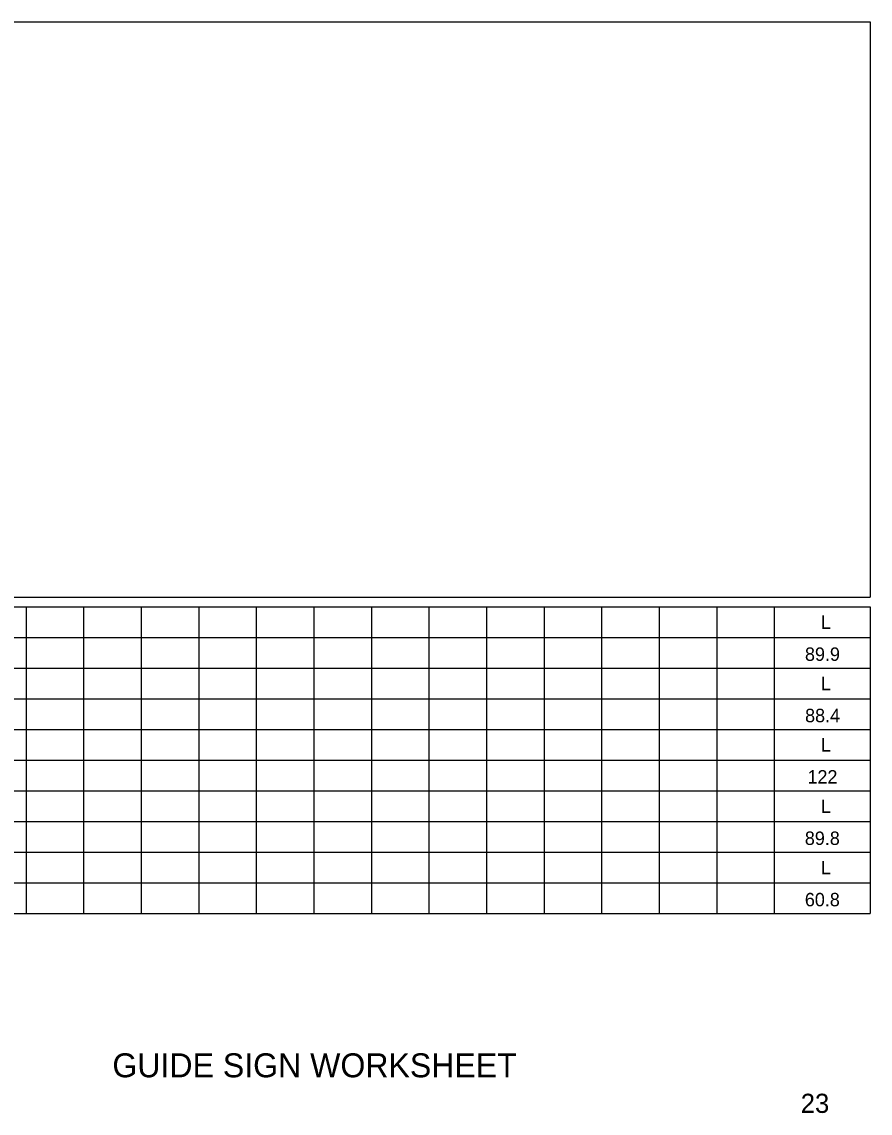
# Model space of a CAD drawing. Extents: x 10268312 to 10268471, y 2141099 to 2141204.
# Drawn here: x 10268426.8 to 10268471, y 2141101.8 to 2141158.7 of the extents above; entities that cross this region are included whole.
import ezdxf

# ---------------------------------------------------------------- set-up
doc = ezdxf.new("R2010")
doc.units = 0
for name, color, linetype in [('SumBoxLines_dp', 7, 'Continuous'), ('SumBoxLinesMin_dp', 7, 'Continuous'), ('TextLabel', 7, 'Continuous'), ('TextMisc', 7, 'Continuous'), ('TextShtNo', 7, 'Continuous')]:
    doc.layers.add(name, color=color, linetype=linetype)

msp = doc.modelspace()

# ---------------------------------------------------------------- linework, layer by layer
at = {"layer": 'SumBoxLines_dp'}
for p, q in [((10268341.73, 2141158.728), (10268470.98, 2141158.728)), ((10268470.98, 2141158.728), (10268470.98, 2141128.728)), ((10268341.73, 2141128.728), (10268470.98, 2141128.728)), ((10268318.48, 2141128.228), (10268470.98, 2141128.228)), ((10268426.98, 2141128.228), (10268426.98, 2141112.228)), ((10268429.98, 2141128.228), (10268429.98, 2141112.228)), ((10268432.98, 2141128.228), (10268432.98, 2141112.228)), ((10268435.98, 2141128.228), (10268435.98, 2141112.228)), ((10268438.98, 2141128.228), (10268438.98, 2141112.228)), ((10268441.98, 2141128.228), (10268441.98, 2141112.228)), ((10268444.98, 2141128.228), (10268444.98, 2141112.228)), ((10268447.98, 2141128.228), (10268447.98, 2141112.228)), ((10268450.98, 2141128.228), (10268450.98, 2141112.228)), ((10268453.98, 2141128.228), (10268453.98, 2141112.228)), ((10268456.98, 2141128.228), (10268456.98, 2141112.228)), ((10268459.98, 2141128.228), (10268459.98, 2141112.228)), ((10268462.98, 2141128.228), (10268462.98, 2141112.228)), ((10268465.98, 2141128.228), (10268465.98, 2141112.228)), ((10268470.98, 2141128.228), (10268470.98, 2141112.228)), ((10268318.48, 2141125.028), (10268470.98, 2141125.028)), ((10268318.48, 2141121.828), (10268470.98, 2141121.828)), ((10268318.48, 2141118.628), (10268470.98, 2141118.628)), ((10268318.48, 2141115.428), (10268470.98, 2141115.428)), ((10268318.48, 2141112.228), (10268470.98, 2141112.228))]:
    msp.add_line(p, q, dxfattribs=at)
at = {"layer": 'SumBoxLinesMin_dp'}
for p, q in [((10268318.48, 2141126.628), (10268470.98, 2141126.628)), ((10268318.48, 2141123.428), (10268470.98, 2141123.428)), ((10268318.48, 2141120.228), (10268470.98, 2141120.228)), ((10268318.48, 2141117.028), (10268470.98, 2141117.028)), ((10268318.48, 2141113.828), (10268470.98, 2141113.828))]:
    msp.add_line(p, q, dxfattribs=at)

# ---------------------------------------------------------------- texts
at = {"layer": 'TextLabel'}
for s, p in [('L', (10268468.411, 2141127.073)), ('89.9', (10268467.582, 2141125.403)), ('L', (10268468.411, 2141123.873)), ('88.4', (10268467.588, 2141122.203)), ('L', (10268468.411, 2141120.673)), ('122', (10268467.712, 2141119.003)), ('L', (10268468.411, 2141117.473)), ('89.8', (10268467.576, 2141115.803)), ('L', (10268468.411, 2141114.273)), ('60.8', (10268467.576, 2141112.603))]:
    msp.add_text(s, height=0.7, dxfattribs=at).set_placement(p)
at = {"layer": 'TextMisc'}
msp.add_text('     GUIDE SIGN WORKSHEET      ', height=1.25, rotation=360, dxfattribs=at).set_placement((10268429.155, 2141103.686))
at = {"layer": 'TextShtNo'}
msp.add_text('23', height=1, rotation=360, dxfattribs=at).set_placement((10268467.361, 2141101.829))

doc.saveas('drawing.dxf')
